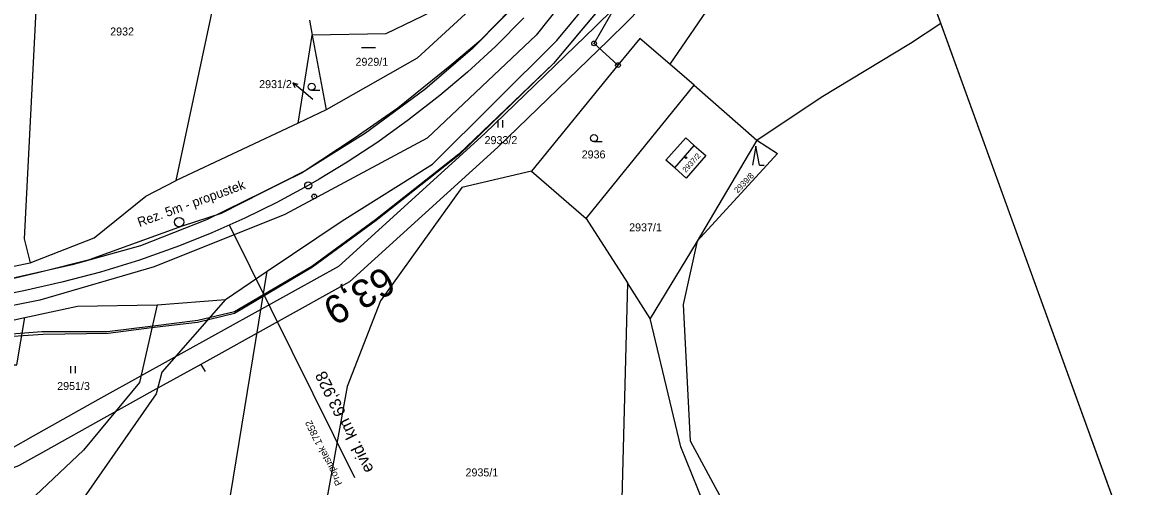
# Model space of a CAD drawing. Extents: x -620552 to -620056, y -1123312 to -1122890.
# Drawn here: x -620295.9 to -620056.1, y -1123143.8 to -1123045.1 of the extents above; entities that cross this region are included whole.
import ezdxf

# ---------------------------------------------------------------- set-up
doc = ezdxf.new("R2010")
doc.units = 0
for name, color, linetype in [('HranDP', 7, 'Continuous'), ('Hranice parcel', 7, 'Continuous'), ('Parcelní čísla', 7, 'Continuous'), ('Pop  PČ popisy', 7, 'Continuous'), ('PS 06-14-01_trasa_sdělovací_nové', 7, 'Continuous'), ('Rámečky', 7, 'Continuous'), ('Rámečky-tisk', 7, 'Continuous'), ('SSZT', 7, 'Continuous'), ('SSZT-DK', 7, 'Continuous'), ('SSZT-TK', 7, 'Continuous'), ('VAS vodovod', 7, 'Continuous'), ('Vnitřní kresba', 7, 'Continuous'), ('Vrstva 1', 7, 'Continuous'), ('Vrstva 13', 7, 'Continuous'), ('Vrstva 19', 7, 'Continuous'), ('Vrstva 3', 7, 'Continuous'), ('Vrstva 7', 7, 'Continuous'), ('Značky bodu BP', 7, 'Continuous'), ('Značky budov', 7, 'Continuous'), ('Značky kultur', 7, 'Continuous'), ('ČD-T', 7, 'Continuous')]:
    doc.layers.add(name, color=color, linetype=linetype)

msp = doc.modelspace()

# ---------------------------------------------------------------- linework, layer by layer
at = {"layer": 'HranDP'}
for p, q in [((-620231.41, -1123063.68), (-620237.39, -1123066.51)), ((-620237.39, -1123066.51), (-620263.28, -1123078.74)), ((-620306.69, -1123098.69), (-620294.3, -1123096.22)), ((-620252.85, -1123104.02), (-620243.96, -1123098.03)), ((-620267.31, -1123105.13), (-620252.85, -1123104.02)), ((-620301.93, -1123109.26), (-620295.45, -1123107.86))]:
    msp.add_line(p, q, dxfattribs=at)
for points in [[(-620243.96, -1123098.03), (-620228.02, -1123087.3), (-620208.81, -1123075.27), (-620182.41, -1123048.95), (-620179.31, -1123045.19), (-620168.12, -1123031.65)], [(-620197.49, -1123039.27), (-620212.08, -1123052.71), (-620231.41, -1123063.68)], [(-620294.3, -1123096.22), (-620280.71, -1123090.89), (-620269.72, -1123082.03), (-620263.28, -1123078.74)], [(-620295.45, -1123107.86), (-620284.26, -1123105.43), (-620267.31, -1123105.13)]]:
    msp.add_lwpolyline(points, dxfattribs=at)
at = {"layer": 'Hranice parcel'}
for p, q in [((-620263.28, -1123078.74), (-620242.46, -1122980.18)), ((-620148.96, -1123040.16), (-620158.39, -1123054.01)), ((-620234.98, -1123044.6), (-620234.38, -1123047.81)), ((-620237.39, -1123066.51), (-620234.38, -1123047.81)), ((-620234.38, -1123047.81), (-620231.41, -1123063.68)), ((-620169.42, -1123054.19), (-620187.77, -1123076.72)), ((-620153.24, -1123058.46), (-620158.39, -1123054.01)), ((-620176.15, -1123086.79), (-620153.24, -1123058.46)), ((-620153.24, -1123058.46), (-620139.89, -1123070.16)), ((-620231.41, -1123063.68), (-620237.39, -1123066.51)), ((-620237.39, -1123066.51), (-620263.28, -1123078.74)), ((-620139.89, -1123070.16), (-620152.59, -1123091.6)), ((-620187.77, -1123076.72), (-620176.15, -1123086.79)), ((-620176.15, -1123086.79), (-620167.39, -1123100.52)), ((-620152.8, -1123091.95), (-620162.55, -1123108.1)), ((-620152.59, -1123091.6), (-620152.8, -1123091.95)), ((-620306.69, -1123098.69), (-620294.3, -1123096.22)), ((-620258.49, -1123186.41), (-620243.96, -1123098.03)), ((-620252.85, -1123104.02), (-620243.96, -1123098.03)), ((-620167.39, -1123100.52), (-620169.58, -1123182.3)), ((-620162.55, -1123108.1), (-620167.39, -1123100.52)), ((-620267.31, -1123105.13), (-620252.85, -1123104.02)), ((-620301.93, -1123109.26), (-620295.45, -1123107.86))]:
    msp.add_line(p, q, dxfattribs=at)
for points in [[(-620289.02, -1123011.5), (-620293.05, -1123041.17), (-620295.61, -1123091.1), (-620294.3, -1123096.22)], [(-620169.42, -1123054.19), (-620174.5, -1123049.57), (-620168, -1123038.2), (-620152.59, -1123026.13)], [(-620243.96, -1123098.03), (-620228.02, -1123087.3), (-620208.81, -1123075.27), (-620182.41, -1123048.95), (-620179.31, -1123045.19), (-620168.12, -1123031.65)], [(-620197.49, -1123039.27), (-620207, -1123041.9), (-620218.72, -1123047.54), (-620234.38, -1123047.81)], [(-620197.49, -1123039.27), (-620212.08, -1123052.71), (-620231.41, -1123063.68)], [(-620139.89, -1123070.16), (-620126.22, -1123060.97), (-620107.28, -1123049.5), (-620100.81, -1123045.29)], [(-620158.39, -1123054.01), (-620164.78, -1123048.5), (-620169.42, -1123054.19)], [(-620159.28, -1123074.39), (-620154.99, -1123069.68), (-620153.24, -1123071.27), (-620150.78, -1123073.44), (-620154.95, -1123078.2), (-620157.37, -1123076.03), (-620159.28, -1123074.39)], [(-620139.89, -1123070.16), (-620135.5, -1123072.99), (-620152.59, -1123091.6)], [(-620187.77, -1123076.72), (-620202.59, -1123080.2), (-620219.89, -1123104.3), (-620226.94, -1123122.55), (-620232.45, -1123152.64), (-620233.85, -1123191.46)], [(-620294.3, -1123096.22), (-620280.71, -1123090.89), (-620269.72, -1123082.03), (-620263.28, -1123078.74)], [(-620152.59, -1123091.6), (-620155.57, -1123105.08), (-620154.07, -1123134.06), (-620143.02, -1123154.56), (-620138.08, -1123176.89), (-620193.14, -1123193.74), (-620221.59, -1123191.7), (-620233.71, -1123192.88), (-620259.81, -1123191.23)], [(-620267.31, -1123105.13), (-620271.09, -1123121.69), (-620283, -1123136.04), (-620303.5, -1123155.32)], [(-620295.45, -1123107.86), (-620284.26, -1123105.43), (-620267.31, -1123105.13)], [(-620252.85, -1123104.02), (-620266.37, -1123119.45), (-620267.54, -1123124.06), (-620286.24, -1123150.98), (-620288.99, -1123164.76), (-620262.29, -1123185.63)], [(-620298.49, -1123117.9), (-620297.19, -1123117.91), (-620295.45, -1123107.86)], [(-620169.58, -1123182.3), (-620139.22, -1123177.02), (-620156.05, -1123135.37), (-620162.55, -1123108.1)]]:
    msp.add_lwpolyline(points, dxfattribs=at)
at = {"layer": 'Pop  PČ popisy'}
for p, q in [((-620236.21, -1123059.88), (-620238.51, -1123057.95)), ((-620238.51, -1123057.95), (-620237.42, -1123058.21)), ((-620238.51, -1123057.95), (-620238.06, -1123058.98)), ((-620234.25, -1123061.52), (-620236.21, -1123059.88))]:
    msp.add_line(p, q, dxfattribs=at)
at = {"layer": 'PS 06-14-01_trasa_sdělovací_nové'}
msp.add_lwpolyline([(-620302.99, -1123100.7), (-620292.4, -1123098.24), (-620281.7, -1123095.56), (-620261.93, -1123088.35), (-620253.64, -1123085.66), (-620244.89, -1123081.19), (-620236.13, -1123076.73), (-620225.47, -1123069.74), (-620216.19, -1123063.28), (-620205.15, -1123054.34), (-620198.59, -1123048.78), (-620192.32, -1123042.45), (-620189.21, -1123039.13), (-620192.93, -1123035.47), (-620189.24, -1123032.05), (-620184.32, -1123027.49), (-620172.92, -1123014.85), (-620170.12, -1123011.86), (-620165.72, -1123007.16), (-620158.18, -1122991.64), (-620154.53, -1122984.74), (-620154, -1122982.93), (-620152.3, -1122977.09), (-620150.63, -1122971.37)], dxfattribs=at)
at = {"layer": 'Rámečky'}
msp.add_line((-620056.07, -1123168.86), (-620157.19, -1122889.6), dxfattribs=at)
at = {"layer": 'Rámečky-tisk'}
msp.add_lwpolyline([(-620450.98, -1123311.85), (-620056.07, -1123168.86), (-620157.19, -1122889.6), (-620552.1, -1123032.6)], dxfattribs=at)
at = {"layer": 'SSZT'}
msp.add_lwpolyline([(-620166.88, -1123010.24), (-620171.39, -1123017.17), (-620176.01, -1123023.63), (-620178.84, -1123027.27), (-620187.42, -1123037.54), (-620200.37, -1123050.67), (-620210.46, -1123059.35), (-620223.07, -1123068.67), (-620236.68, -1123077.14), (-620256.88, -1123087.09), (-620270.91, -1123092.6), (-620285.4, -1123096.67), (-620303.6, -1123100.76), (-620319.9, -1123103.93), (-620331.96, -1123106.25), (-620430.51, -1123125.18), (-620444.41, -1123127.82), (-620476.1, -1123133.9), (-620498.92, -1123138.28), (-620512.26, -1123140.83), (-620512.86, -1123140.95)], dxfattribs=at)
at = {"layer": 'SSZT-DK'}
msp.add_lwpolyline([(-620133.24, -1122955.74), (-620133.43, -1122956.64), (-620137.1, -1122967.18), (-620142.13, -1122981.67), (-620150.09, -1123001.93), (-620153.27, -1123011.66), (-620162.86, -1123027.53), (-620167.45, -1123035.13), (-620177.31, -1123046.87), (-620183.14, -1123053.82), (-620203.25, -1123073.11), (-620220.92, -1123087.08), (-620234.47, -1123097), (-620250.94, -1123106.67), (-620258.73, -1123108.48), (-620268.16, -1123109.67), (-620277.94, -1123110.89), (-620291.83, -1123110.91), (-620302.99, -1123111.77)], dxfattribs=at)
at = {"layer": 'SSZT-TK'}
msp.add_lwpolyline([(-620135.22, -1122950.28), (-620135.4, -1122951.34), (-620146.6, -1122984.04), (-620155.29, -1123003.62), (-620165.83, -1123021.36), (-620186.83, -1123047.79), (-620210, -1123069.75), (-620240.2, -1123085.98), (-620267.98, -1123097.08), (-620292.31, -1123104.15), (-620332.1, -1123112.12), (-620382.38, -1123122.06), (-620466.84, -1123137.57), (-620511.01, -1123146.08)], dxfattribs=at)
at = {"layer": 'VAS vodovod'}
for points in [[(-620149.01, -1123008.86), (-620153.26, -1123021.35), (-620170.32, -1123042.17), (-620174.28, -1123046.08), (-620197.72, -1123068.73), (-620228.79, -1123097.03), (-620270.23, -1123119.97), (-620279.98, -1123125.39), (-620293.71, -1123133.06), (-620298.47, -1123135.79), (-620300.47, -1123136.51), (-620304.69, -1123137.51), (-620306.42, -1123137.92), (-620355.45, -1123149.02), (-620380.2, -1123152.84), (-620387.1, -1123153.74), (-620431.25, -1123159.48), (-620484.75, -1123167.02), (-620502.03, -1123170.86)], [(-620143.62, -1123010.63), (-620143.76, -1123012.48), (-620147.75, -1123024.43), (-620148.88, -1123025.86), (-620151.68, -1123028.7), (-620167.48, -1123044.99), (-620171.49, -1123048.94), (-620194.98, -1123071.65), (-620226.44, -1123100.3), (-620258.1, -1123117.83), (-620268.29, -1123123.47), (-620278.03, -1123128.88), (-620291.74, -1123136.54), (-620296.78, -1123139.43), (-620299.32, -1123140.35), (-620305.52, -1123141.82), (-620338.85, -1123149.47), (-620354.7, -1123152.95), (-620379.64, -1123156.8), (-620430.73, -1123163.45), (-620484.29, -1123170.42), (-620500.86, -1123174.1)], [(-620258.1, -1123117.83), (-620257.82, -1123118.24), (-620257.14, -1123119.31)]]:
    msp.add_lwpolyline(points, dxfattribs=at)
at = {"layer": 'Vnitřní kresba'}
msp.add_line((-620157.37, -1123076.03), (-620153.24, -1123071.27), dxfattribs=at)
at = {"layer": 'Vrstva 1'}
for points in [[(-620302.99, -1123100.7), (-620292.4, -1123098.24), (-620281.7, -1123095.56), (-620261.93, -1123088.35), (-620253.64, -1123085.66), (-620236.13, -1123076.73), (-620225.47, -1123069.74), (-620216.19, -1123063.28), (-620205.15, -1123054.34), (-620198.59, -1123048.78), (-620192.32, -1123042.45), (-620189.21, -1123039.13), (-620192.93, -1123035.47), (-620189.24, -1123032.05), (-620184.32, -1123027.49), (-620172.92, -1123014.85), (-620170.12, -1123011.86), (-620165.72, -1123007.16), (-620158.18, -1122991.64), (-620154.53, -1122984.74), (-620154, -1122982.93), (-620152.3, -1122977.09), (-620150.63, -1122971.37)], [(-620189.42, -1123044.16), (-620195.41, -1123050.18), (-620201.42, -1123055.71), (-620207.3, -1123060.67), (-620213.93, -1123065.85), (-620220.45, -1123070.54), (-620226.96, -1123074.82), (-620232.91, -1123078.44), (-620235.25, -1123079.78), (-620241.89, -1123083.37), (-620248.71, -1123086.73), (-620255.76, -1123089.87), (-620262.62, -1123092.63), (-620271.12, -1123095.65), (-620279.4, -1123098.2), (-620287.58, -1123100.35), (-620295.67, -1123102.19), (-620303.02, -1123103.7)]]:
    msp.add_lwpolyline(points, dxfattribs=at)
at = {"layer": 'Vrstva 13'}
msp.add_circle((-620262.69, -1123087.56), 1, dxfattribs=at)
at = {"layer": 'Vrstva 19'}
msp.add_line((-620225.37, -1123141.98), (-620251.96, -1123088.19), dxfattribs=at)
at = {"layer": 'Vrstva 7'}
msp.add_line((-620233.94, -1123082.09), (-620234.03, -1123082.14), dxfattribs=at)
for centre, radius in [((-620235.25, -1123079.78), 0.75), ((-620233.98, -1123082.12), 0.5)]:
    msp.add_circle(centre, radius, dxfattribs=at)
at = {"layer": 'Značky bodu BP'}
for centre, radius in [((-620174.5, -1123049.57), 0.5), ((-620174.5, -1123049.57), 0.0303), ((-620169.42, -1123054.19), 0.5), ((-620169.42, -1123054.19), 0.0303)]:
    msp.add_circle(centre, radius, dxfattribs=at)
at = {"layer": 'Značky budov'}
msp.add_circle((-620154.96, -1123073.88), 0.175, dxfattribs=at)
at = {"layer": 'Značky kultur'}
for p, q in [((-620223.92, -1123050.46), (-620220.92, -1123050.46)), ((-620234.53, -1123059.54), (-620232.78, -1123059.54)), ((-620194.87, -1123067.42), (-620194.87, -1123065.92)), ((-620193.87, -1123067.42), (-620193.87, -1123065.92)), ((-620174.52, -1123070.46), (-620172.77, -1123070.46)), ((-620140.1, -1123071.45), (-620140.85, -1123075.45)), ((-620139.35, -1123075.45), (-620140.1, -1123071.45)), ((-620139.35, -1123075.45), (-620138.35, -1123075.45)), ((-620285.7, -1123119.71), (-620285.7, -1123118.21)), ((-620284.7, -1123119.71), (-620284.7, -1123118.21))]:
    msp.add_line(p, q, dxfattribs=at)
for centre in [(-620234.53, -1123058.79), (-620174.52, -1123069.71)]:
    msp.add_circle(centre, 0.75, dxfattribs=at)
at = {"layer": 'ČD-T'}
msp.add_lwpolyline([(-620133.15, -1122955.98), (-620133.25, -1122956.41), (-620136.91, -1122966.94), (-620141.94, -1122981.44), (-620149.9, -1123001.7), (-620153.17, -1123011.69), (-620162.64, -1123027.32), (-620167.44, -1123035.18), (-620176.91, -1123046.42), (-620183.1, -1123053.85), (-620203.17, -1123073.24), (-620220.83, -1123087.24), (-620234.31, -1123097.18), (-620250.89, -1123107.04), (-620258.79, -1123108.89), (-620268.53, -1123110.05), (-620277.75, -1123111.28), (-620291.59, -1123111.44), (-620302.16, -1123112.16)], dxfattribs=at)

# ---------------------------------------------------------------- texts
at = {"layer": 'Parcelní čísla'}
for s, p in [('2932', (-620277.33, -1123047.89)), ('2929/1', (-620225.2, -1123054.33)), ('2931/2', (-620245.67, -1123059.08)), ('2933/2', (-620197.77, -1123070.99)), ('2936', (-620177.14, -1123074.03)), ('2937/1', (-620167.05, -1123089.54)), ('2951/3', (-620288.59, -1123123.28)), ('2935/1', (-620201.82, -1123141.65))]:
    msp.add_text(s, height=1.7, dxfattribs=at).set_placement(p)
for s, height, rotation, p in [('2937/2', 1.139, 48, (-620155, -1123077.11)), ('2939/8', 1.254, 46, (-620143.98, -1123081.5))]:
    msp.add_text(s, height=height, rotation=rotation, dxfattribs=at).set_placement(p)
at = {"layer": 'Vrstva 19'}
for s, height, p in [('evid. km 63,928', 2.5, (-620221.28, -1123140.2)), ('Propustek 17852', 1.5, (-620227.97, -1123143.18))]:
    msp.add_text(s, height=height, rotation=116.0458, dxfattribs=at).set_placement(p)
at = {"layer": 'Vrstva 3'}
msp.add_text('Rez. 5m - propustek', height=2, rotation=19.9058, dxfattribs=at).set_placement((-620271.1, -1123088.62))
at = {"layer": 'Vrstva 7'}
msp.add_text('63,9', height=6, rotation=209.9159, dxfattribs=at).set_placement((-620219.08, -1123096.76))

doc.saveas('drawing.dxf')
